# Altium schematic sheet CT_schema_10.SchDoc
size 209 x 185 mm
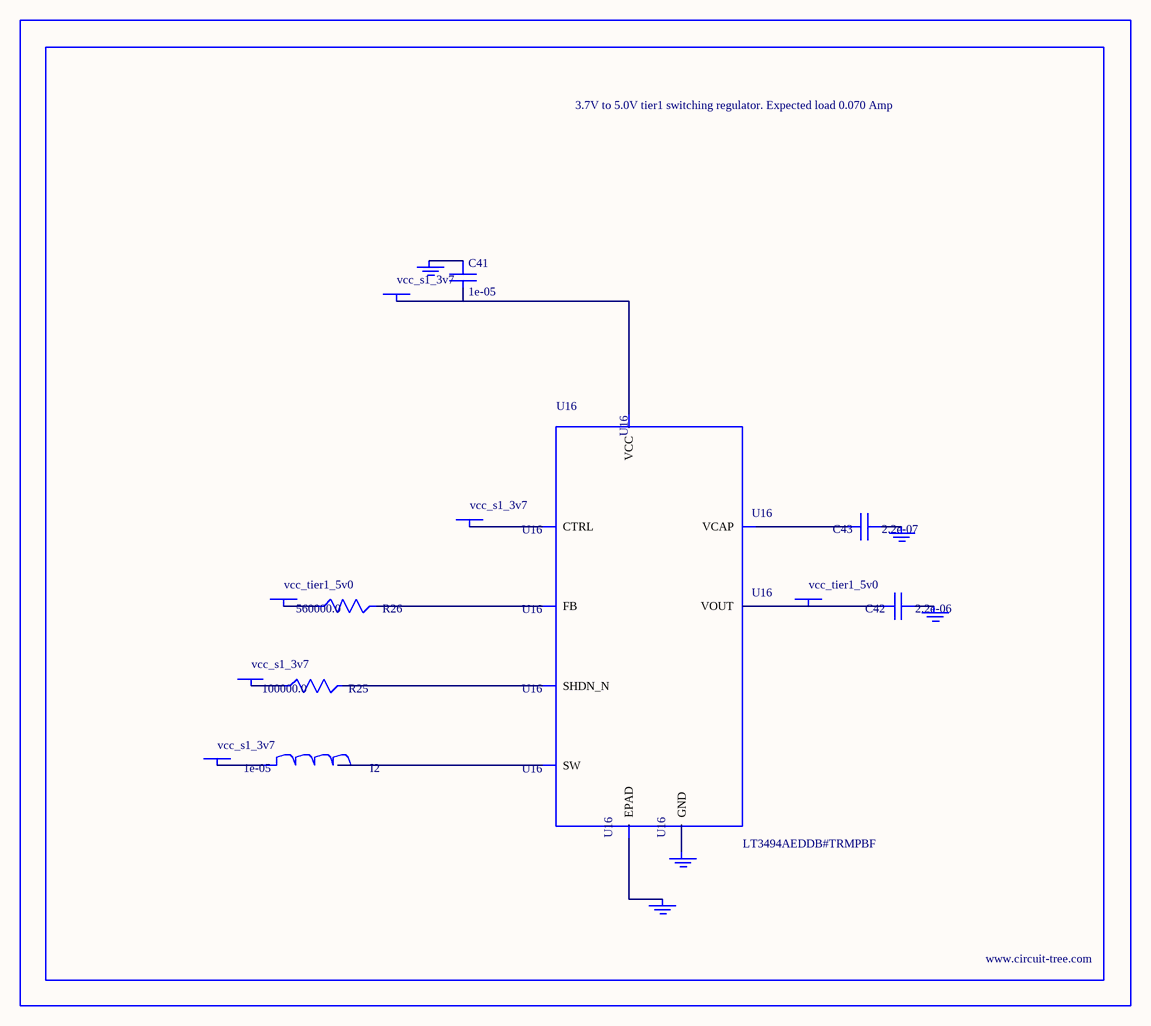
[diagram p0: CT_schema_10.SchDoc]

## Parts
BORDER9  (no value)
C41  1e-05  [C1210]
C42  2.2e-06  [C0603]
C43  2.2e-07  [C0603]
GND_INSTANCE_9_0  (no value)
GND_INSTANCE_9_1  (no value)
GND_INSTANCE_9_2  (no value)
GND_INSTANCE_9_3  (no value)
GND_INSTANCE_9_4  (no value)
I2  1e-05  [L1210]
POWER_INSTANCE_9_0  vcc_s1_3v7
POWER_INSTANCE_9_1  vcc_s1_3v7
POWER_INSTANCE_9_2  vcc_s1_3v7
POWER_INSTANCE_9_3  vcc_s1_3v7
POWER_INSTANCE_9_4  vcc_tier1_5v0
POWER_INSTANCE_9_5  vcc_tier1_5v0
R25  100000.0  [R0603]
R26  560000.0  [R0603]
U16  LT3494AEDDB#TRMPBF  [DFN-8_DDB]

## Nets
NetC41_1: C41.1 GND_INSTANCE_9_0.0(GND)
NetC41_2: C41.2 POWER_INSTANCE_9_1.0(PWR) U16.3(VCC)
NetC42_1: C42.1 GND_INSTANCE_9_1.0(GND)
NetC42_2: C42.2 POWER_INSTANCE_9_5.0(PWR) U16.7(VOUT)
NetC43_1: C43.1 GND_INSTANCE_9_2.0(GND)
NetC43_2: C43.2 U16.8(VCAP)
NetGND_INSTANCE_9_3_0: GND_INSTANCE_9_3.0(GND) U16.9(EPAD)
NetGND_INSTANCE_9_4_0: GND_INSTANCE_9_4.0(GND) U16.2(GND)
NetI2_1: I2.1 POWER_INSTANCE_9_0.0(PWR)
NetI2_2: I2.2 U16.1(SW)
NetPOWER_INSTANCE_9_2_0: POWER_INSTANCE_9_2.0(PWR) U16.4(CTRL)
NetPOWER_INSTANCE_9_3_0: POWER_INSTANCE_9_3.0(PWR) R25.1
NetPOWER_INSTANCE_9_4_0: POWER_INSTANCE_9_4.0(PWR) R26.1
NetR25_2: R25.2 U16.5(SHDN_N)
NetR26_2: R26.2 U16.6(FB)

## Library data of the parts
BORDER9 = BORDER_PAGE9
C41 = C1210C106K5PACTU
C42 = GRM188R61H225KE1115D
C43 = C0603C224K3RAC
GND_INSTANCE_9_0-GND_INSTANCE_9_4 = GND
I2 = CBC3225T100MR
POWER_INSTANCE_9_0-POWER_INSTANCE_9_5 = PWR
R25 = RC0603JR-07100KL
R26 = RC0603JR-07560KL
